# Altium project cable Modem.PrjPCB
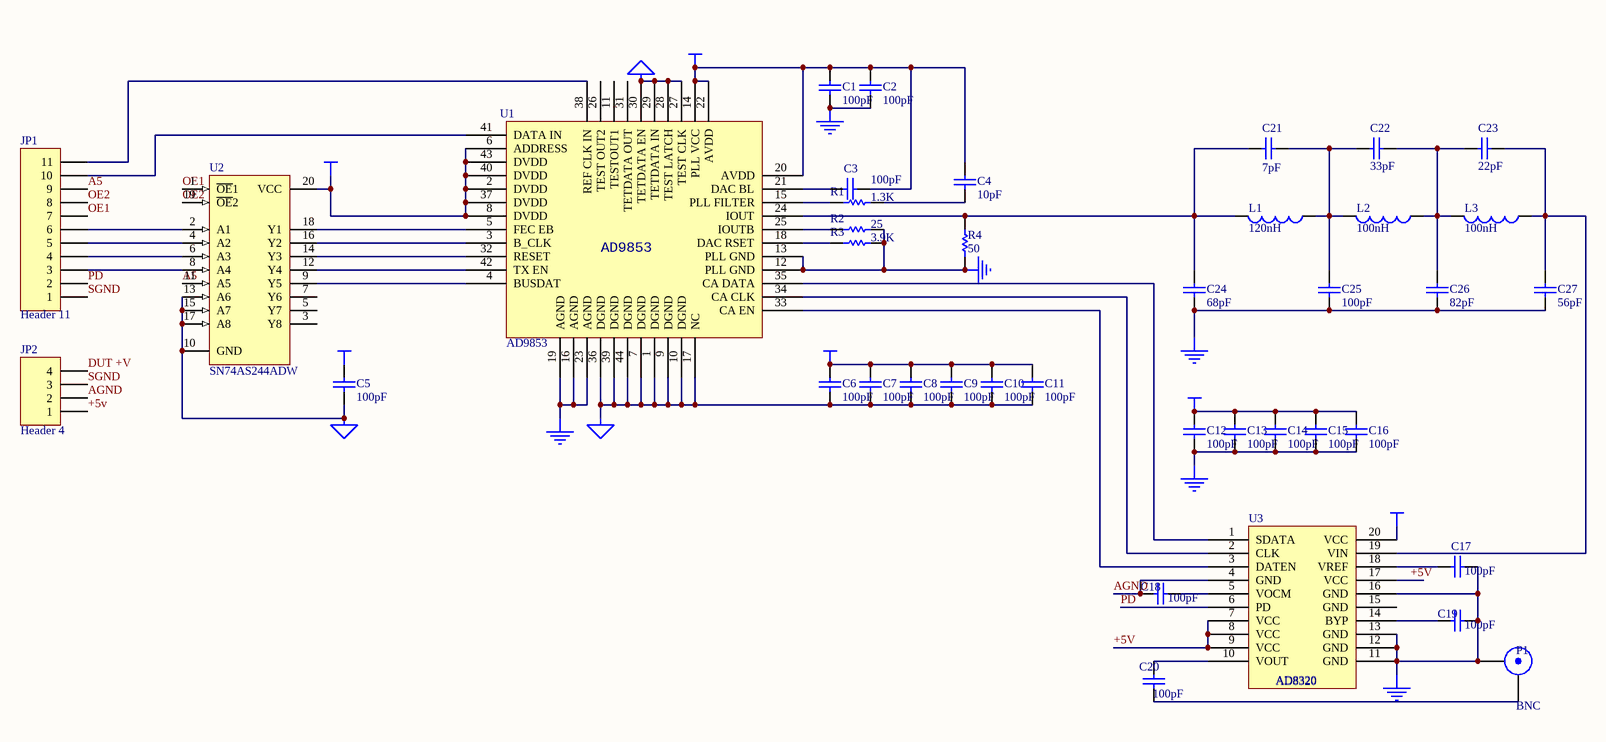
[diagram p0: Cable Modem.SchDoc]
1 sheet, 40 parts. Net scope: global (net labels, ports and power ports of the same name join across sheets).
Board file: Cable Modem.PcbDoc

## Sheet Cable Modem.SchDoc
size B

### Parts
C1  100pF  [CC2012-0805]
C2  100pF  [CC2012-0805]
C3  100pF  [CC2012-0805]
C4  10pF  [CC2012-0805]
C5  100pF  [CC2012-0805]
C6  100pF  [CC2012-0805]
C7  100pF  [CC2012-0805]
C8  100pF  [CC2012-0805]
C9  100pF  [CC2012-0805]
C10  100pF  [CC2012-0805]
C11  100pF  [CC2012-0805]
C12  100pF  [CC2012-0805]
C13  100pF  [CC2012-0805]
C14  100pF  [CC2012-0805]
C15  100pF  [CC2012-0805]
C16  100pF  [CC2012-0805]
C17  100pF  [CC2012-0805]
C18  100pF  [CC2012-0805]
C19  100pF  [CC2012-0805]
C20  100pF  [CC2012-0805]
C21  7pF  [CC2012-0805]
C22  33pF  [CC2012-0805]
C23  22pF  [CC2012-0805]
C24  68pF  [CC2012-0805]
C25  100pF  [CC2012-0805]
C26  82pF  [CC2012-0805]
C27  56pF  [CC2012-0805]
JP1  Header 11  [HDR1X11]
JP2  Header 4  [HDR1X4]
L1  120nH  [C1005-0402]
L2  100nH  [C1005-0402]
L3  100nH  [C1005-0402]
P1  BNC  [BNC_RA CON]
R1  1.3K  [R2012-0805]
R2  25  [R2012-0805]
R3  3.9K  [R2012-0805]
R4  50  [R2012-0805]
U1  AD9853  [QFP10X10-G44/N]
U2  SN74AS244ADW  [SO-G20/G7.1]
U3  AD8320  [SO-G20]

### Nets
+5V: C1.2 C2.2 C3.2 C4.1 C12.2 C13.2 C14.2 C15.2 C16.2 JP2.1 U1.14(PLL_VCC) U1.20(AVDD) U1.22(AVDD) U3.7(VCC) U3.8(VCC) U3.9(VCC) U3.17(VCC) U3.20(VCC)
AGND: C1.1 C2.1 C12.1 C13.1 C14.1 C15.1 C16.1 C17.1 C18.1 C19.2 C24.2 C25.2 C26.2 C27.2 JP2.2 P1.2(Y) R2.2 R3.2 R4.1 U1.12(PLL_GND) U1.13(PLL_GND) U1.16(AGND) U1.19(AGND) U1.23(AGND) U3.4(GND) U3.11(GND) U3.12(GND) U3.13(GND) U3.16(GND)
DUT +V: C5.2 C6.2 C7.2 C8.2 C9.2 C10.2 C11.2 JP2.4 U1.2(DVDD) U1.6(ADDRESS) U1.8(DVDD) U1.37(DVDD) U1.40(DVDD) U1.43(DVDD) U2.20(VCC)
SGND: C5.1 C6.1 C7.1 C8.1 C9.1 C10.1 C11.1 JP1.1 JP2.3 U1.1(DGND) U1.7(DGND) U1.9(DGND) U1.10(DGND) U1.17(NC) U1.27(TEST_CLK) U1.28(TEST_LATCH) U1.29(TETDATA_IN) U1.30(TETDATA_EN) U1.36(DGND) U1.39(DGND) U1.44(DGND) U2.10(GND) U2.13(A6) U2.15(A7) U2.17(A8)
A5: JP1.9 U2.11(A5)
OE1: JP1.7 U2.1(~{OE}1)
OE2: JP1.8 U2.19(~{OE}2)
PD: JP1.2 U3.6(PD)
NetC3_1: C3.1 U1.21(DAC_BL)
NetC4_2: C4.2 R1.2
NetC17_2: C17.2 U3.18(VREF)
NetC18_2: C18.2 U3.5(VOCM)
NetC19_1: C19.1 U3.14(BYP)
NetC20_1: C20.1 P1.1(X)
NetC20_2: C20.2 U3.10(VOUT)
NetC21_1: C21.1 C24.1 L1.2 R4.2 U1.24(IOUT)
NetC21_2: C21.2 C22.1 C25.1 L1.1 L2.2
NetC22_2: C22.2 C23.1 C26.1 L2.1 L3.2
NetC23_2: C23.2 C27.1 L3.1 U3.19(VIN)
NetJP1_3: JP1.3 U2.8(A4)
NetJP1_4: JP1.4 U2.6(A3)
NetJP1_5: JP1.5 U2.4(A2)
NetJP1_6: JP1.6 U2.2(A1)
NetJP1_10: JP1.10 U1.41(DATA_IN)
NetJP1_11: JP1.11 U1.38(REF_CLK_IN)
NetR1_1: R1.1 U1.15(PLL_FILTER)
NetR2_1: R2.1 U1.25(IOUTB)
NetR3_1: R3.1 U1.18(DAC_RSET)
NetU1_3: U1.3(B_CLK) U2.16(Y2)
NetU1_4: U1.4(BUSDAT) U2.9(Y5)
NetU1_5: U1.5(FEC_EB) U2.18(Y1)
NetU1_32: U1.32(RESET) U2.14(Y3)
NetU1_33: U1.33(CA_EN) U3.3(DATEN)
NetU1_34: U1.34(CA_CLK) U3.2(CLK)
NetU1_35: U1.35(CA_DATA) U3.1(SDATA)
NetU1_42: U1.42(TX_EN) U2.12(Y4)

Not connected (* = marked no-connect by the designer): U1 11(TESTOUT1) 26(TEST_OUT2) 31(TETDATA_OUT); U2 3(Y8) 5(Y7) 7(Y6); U3 15(GND)

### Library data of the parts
C1-C20 = Cap: Capacitor; Manufacturer: Generic Components; Class I: Passive
C21-C27 = Cap Semi: Capacitor (Semiconductor SIM Model); Manufacturer: Generic Components; Class I: Passive
JP1 = Header 11: Header, 11-Pin; Manufacturer: Generic Components; Class I: Connector
JP2 = Header 4: Header, 4-Pin; Manufacturer: Generic Components; Class I: Connector
L1-L3 = Inductor: Manufacturer: Generic Components; Class I: Passive
P1 = BNC: BNC Elbow Connector; Manufacturer: Generic Components; Class II: RF Coaxial
R1-R4 = Res1: Resistor; Manufacturer: Generic Components; Class I: Passive
U1 = AD9853: Programmable Digital QPSK/16-QAM Modulator
U2 = SN74AS244ADW: Octal Buffer/Driver with 3-State Outputs; Manufacturer: Texas Instruments; Package Information: Latest Revision: Dec-1998; Class I: Logic; Class II: Buffer/Line Driver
